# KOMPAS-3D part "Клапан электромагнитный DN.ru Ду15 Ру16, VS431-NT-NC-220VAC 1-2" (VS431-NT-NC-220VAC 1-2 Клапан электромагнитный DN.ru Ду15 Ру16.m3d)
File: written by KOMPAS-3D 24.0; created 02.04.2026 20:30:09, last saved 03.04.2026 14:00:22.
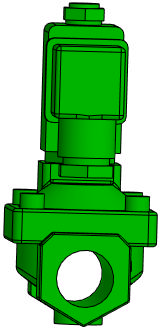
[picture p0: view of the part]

Document properties: Автор: artio; Полное имя файла: C:\Users\artio\OneDrive\Рабочий стол\Клапан электромагнитный DN.ru\VS431\VS431-NT-NC\VS431-NT-NC-220VAC\Ду15\VS431-NT-NC-220VAC 1-2 Клапан электромагнитный DN.ru Ду15 Ру16.m3d

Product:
- Body: Тело 1  | qty 1
    Масса: 1.030062
- Part/product: Клапан электромагнитный DN.ru Ду15 Ру16  | designation VS431-NT-NC-220VAC 1-2
    Масса: 0.732
    Раздел спецификации: Прочие изделия
    Примечание: D130-04661
    additional columns: ef56311e-7521-43dc-8291-0e6108b3d81d; VS400-ET-NC-220VAC 1-2; artio; c; Шероховатость не задана; Да

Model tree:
1. Операция без истории:1

Expressions: VS431-NT-NC-220VAC 1-2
